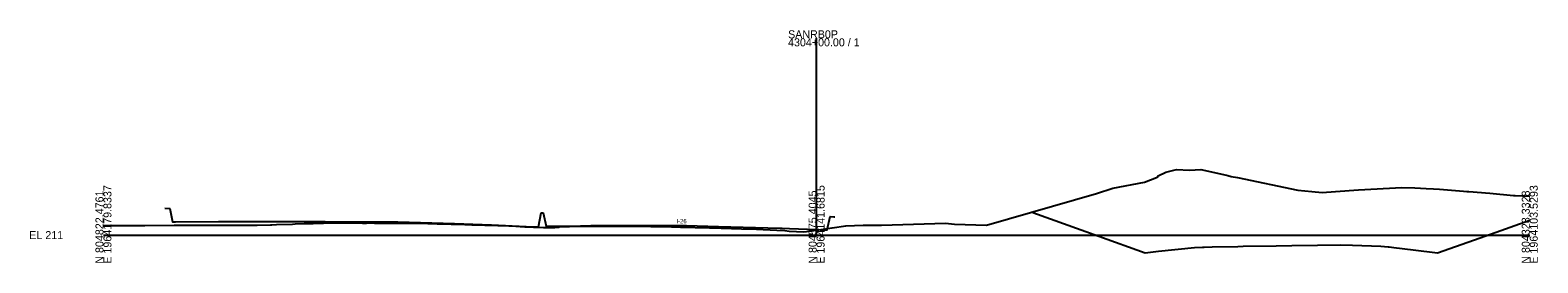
# Model space of a CAD drawing. Extents: x 1995641 to 1997170, y 790368 to 809963.
# Drawn here: x 1996641 to 1997170, y 794868 to 794950 of the extents above; entities that cross this region are included whole.
import ezdxf

# ---------------------------------------------------------------- set-up
doc = ezdxf.new("R2010")
doc.units = 0
for name, color, linetype in [('Default', 7, 'Continuous'), ('RD_GPK_XS_Cell', 7, 'Continuous'), ('RD_Sketch1', 7, 'Continuous'), ('RD_XS_ExGround', 7, 'Continuous'), ('RD_XS_Pave', 7, 'Continuous')]:
    doc.layers.add(name, color=color, linetype=linetype)

msp = doc.modelspace()

# ---------------------------------------------------------------- linework, layer by layer
at = {"layer": 'RD_GPK_XS_Cell'}
for p, q in [((1996917.06, 794878.11), (1996917.06, 794946.99)), ((1996667.06, 794878.11), (1996917.06, 794878.11)), ((1996917.06, 794878.11), (1997167.06, 794878.11))]:
    msp.add_line(p, q, dxfattribs=at)
at = {"layer": 'RD_XS_ExGround'}
msp.add_lwpolyline([(1996667.06, 794881.48), (1996669.71, 794881.48), (1996678.23, 794881.47), (1996681.56, 794881.5), (1996691.85, 794881.54), (1996695.45, 794881.55), (1996701.08, 794881.56), (1996705.85, 794881.56), (1996707.79, 794881.55), (1996710.03, 794881.54), (1996715.01, 794881.54), (1996718.2, 794881.54), (1996720.89, 794881.57), (1996725.65, 794881.68), (1996726.1, 794881.69), (1996727.7, 794881.84), (1996733.31, 794881.99), (1996734.29, 794882.02), (1996737.39, 794882.13), (1996738.29, 794882.16), (1996739.34, 794882.2), (1996740.15, 794882.22), (1996740.52, 794882.23), (1996742.75, 794882.27), (1996744.14, 794882.3), (1996746.05, 794882.39), (1996747.04, 794882.41), (1996748, 794882.4), (1996749.01, 794882.41), (1996752.62, 794882.39), (1996757.84, 794882.29), (1996759.22, 794882.31), (1996760.56, 794882.36), (1996762.05, 794882.34), (1996773.56, 794882.3), (1996777.5, 794882.29), (1996784.01, 794882.1), (1996793.72, 794881.83), (1996794.62, 794881.81), (1996796.24, 794881.75), (1996805.26, 794881.48), (1996809.17, 794881.39), (1996811.66, 794881.25), (1996813.12, 794881.18), (1996813.67, 794881.08), (1996814.82, 794881.04), (1996817.81, 794880.95), (1996821.29, 794880.79), (1996821.87, 794880.77), (1996822.35, 794880.78), (1996823.38, 794880.79), (1996825.32, 794880.83), (1996825.85, 794880.84), (1996826.2, 794880.93), (1996826.8, 794880.93), (1996827.17, 794881.07), (1996827.77, 794881.09), (1996830.43, 794881.17), (1996845.76, 794881.25), (1996846.85, 794881.26), (1996858.92, 794881.16), (1996863.04, 794881.12), (1996869.3, 794880.94), (1996879.56, 794880.67), (1996880.04, 794880.65), (1996890.78, 794880.31), (1996895.95, 794880.16), (1996903.08, 794879.85), (1996905.89, 794879.72), (1996907.42, 794879.53), (1996912.6, 794879.21), (1996917.06, 794879.86), (1996922.53, 794880.65), (1996927.35, 794881.31), (1996933.4, 794881.57), (1996939.85, 794881.64), (1996962.21, 794882.31), (1996965.36, 794881.9), (1996976.56, 794881.65), (1997015.19, 794892.72), (1997020.94, 794894.52), (1997032.02, 794896.61), (1997036.21, 794898.27), (1997036.7, 794898.47), (1997036.74, 794898.9), (1997039.51, 794900.2), (1997043.24, 794901.07), (1997047.74, 794900.81), (1997051.72, 794901.07), (1997059.68, 794899.28), (1997061.25, 794898.92), (1997062.33, 794898.66), (1997064.55, 794898.22), (1997085.73, 794893.89), (1997090.68, 794893.42), (1997094.33, 794893.08), (1997098.98, 794893.38), (1997107.01, 794893.92), (1997117.88, 794894.6), (1997122.1, 794894.72), (1997126.83, 794894.61), (1997130.79, 794894.43), (1997133.31, 794894.29), (1997135.44, 794894.16), (1997143.87, 794893.47), (1997145.02, 794893.38), (1997145.7, 794893.32), (1997153.05, 794892.74), (1997161.4, 794892.02), (1997161.97, 794891.97), (1997167.06, 794891.71)], dxfattribs=at)
at = {"layer": 'RD_XS_Pave'}
for points in [[(1996688.62, 794887.5), (1996690.3, 794887.46), (1996691.3, 794882.77), (1996692.34, 794882.78), (1996707.41, 794882.93), (1996721.5, 794882.9), (1996737.48, 794882.88), (1996744.74, 794882.84), (1996760.96, 794882.75), (1996767.41, 794882.74), (1996770.29, 794882.74), (1996790.08, 794882.12), (1996803.11, 794881.71), (1996815.26, 794881.16), (1996819.52, 794880.96), (1996820.54, 794885.91), (1996821.23, 794885.9), (1996822.25, 794881.21), (1996834.27, 794881.37), (1996837.86, 794881.43), (1996838.66, 794881.44), (1996859.97, 794881.47), (1996871.47, 794881.49), (1996882.64, 794881.17), (1996904.29, 794880.57), (1996904.36, 794880.57), (1996904.95, 794880.55), (1996907.59, 794880.43), (1996917.06, 794880.06), (1996918.35, 794880.01), (1996920.76, 794879.92), (1996921.79, 794884.58), (1996923.13, 794884.56), (1996923.5, 794884.56)], [(1996992.86, 794886.07), (1997016.03, 794877.77), (1997032.24, 794871.96), (1997036.91, 794872.45), (1997049.5, 794873.78), (1997052.38, 794873.91), (1997052.95, 794873.92), (1997055.72, 794873.96), (1997064.77, 794874.16), (1997066.62, 794874.2), (1997078.17, 794874.36), (1997083.66, 794874.44), (1997092.61, 794874.57), (1997100.7, 794874.68), (1997104.94, 794874.54), (1997114.9, 794874.19), (1997117.38, 794874.03), (1997117.74, 794874.01), (1997119.37, 794873.81), (1997126.23, 794872.96), (1997134.7, 794871.92), (1997151.63, 794877.86), (1997167.06, 794883.33)]]:
    msp.add_lwpolyline(points, dxfattribs=at)

# ---------------------------------------------------------------- texts
at = {"layer": 'Default'}
msp.add_text('-', height=0.0001, dxfattribs=at).set_placement((1996667.06, 794878.11))
msp.add_text('-', height=0.0001, dxfattribs=at).set_placement((1996667.06, 794878.11))
at = {"layer": 'RD_GPK_XS_Cell'}
for s, p in [('4304+00.00 / 1', (1996907.06, 794944.19)), ('SANRB0P', (1996907.06, 794946.99)), ('EL 211', (1996641.06, 794876.71))]:
    msp.add_text(s, height=2.8, dxfattribs=at).set_placement(p)
for s, p in [('N 804822.4761', (1996667.06, 794868.11)), ('E 1964179.8337', (1996669.86, 794868.11)), ('N 804575.4045', (1996917.06, 794868.11)), ('E 1964141.6815', (1996919.86, 794868.11)), ('N 804328.3328', (1997167.06, 794868.11)), ('E 1964103.5293', (1997169.86, 794868.11))]:
    msp.add_text(s, height=2.8, rotation=90, dxfattribs=at).set_placement(p)
at = {"layer": 'RD_Sketch1'}
for s, p in [('212.95', (1996916.85, 794879.96)), ('212.74', (1996916.85, 794879.76))]:
    msp.add_text(s, height=0.1, dxfattribs=at).set_placement(p)
at = {"layer": 'RD_XS_Pave'}
msp.add_text('I-26', height=1.5, dxfattribs=at).set_placement((1996867.93, 794882.23))

doc.saveas('drawing.dxf')
